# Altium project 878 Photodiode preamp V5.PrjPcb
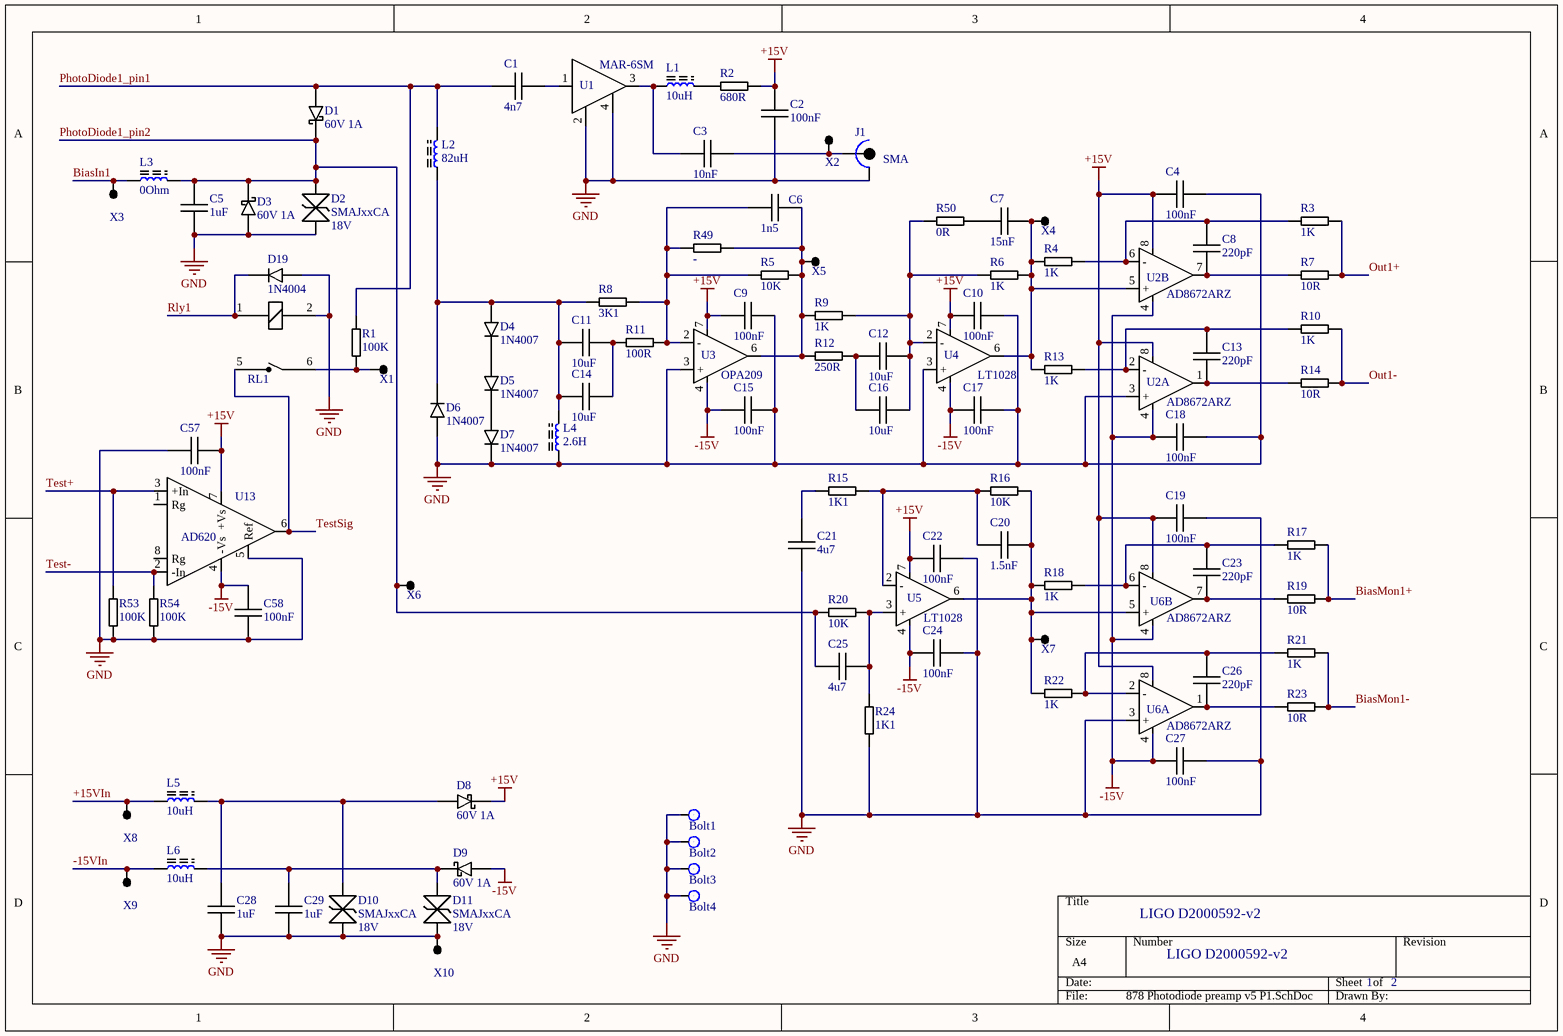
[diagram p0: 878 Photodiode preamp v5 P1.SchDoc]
2 sheets, 182 parts. Net scope: global (net labels, ports and power ports of the same name join across sheets).
Board file: 878 Photodiode preamp V5.PcbDoc
Sheets:
  878 Photodiode preamp v5 P1.SchDoc
  878 Photodiode preamp v5 P2.SchDoc

## Sheet 878 Photodiode preamp v5 P1.SchDoc
size A4

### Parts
Bolt1  Bolt M3  [BOLT]  (value not drawn)
Bolt2  Bolt M3  [BOLT]  (value not drawn)
Bolt3  Bolt M3  [BOLT]  (value not drawn)
Bolt4  Bolt M3  [BOLT]  (value not drawn)
C1  value 4n7  [HS0805Long]  (hidden comment: Cap200)
C2  value 100nF  [HS0805Long]  (hidden comment: Cap200)
C3  value 10nF  [HS0805Long]  (hidden comment: Cap200)
C4  value 100nF  [HS0805Long]  (hidden comment: Cap200)
C5  value 1uF  [HS0805Long]  (hidden comment: Cap200)
C6  value 1n5  [HS0805Long]  (hidden comment: Cap200)
C7  value 15nF  [HS0805Long]  (hidden comment: Cap200)
C8  value 220pF  [HS0805Long]  (hidden comment: Cap200)
C9  value 100nF  [HS0805Long]  (hidden comment: Cap200)
C10  value 100nF  [HS0805Long]  (hidden comment: Cap200)
C11  value 10uF  [MKS2 7.2 11]  (hidden comment: Cap200)
C12  value 10uF  [MKS2 7.2 11]  (hidden comment: Cap200)
C13  value 220pF  [HS0805Long]  (hidden comment: Cap200)
C14  value 10uF  [MKS2 7.2 11]  (hidden comment: Cap200)
C15  value 100nF  [HS0805Long]  (hidden comment: Cap200)
C16  value 10uF  [MKS2 7.2 11]  (hidden comment: Cap200)
C17  value 100nF  [HS0805Long]  (hidden comment: Cap200)
C18  value 100nF  [HS0805Long]  (hidden comment: Cap200)
C19  value 100nF  [HS0805Long]  (hidden comment: Cap200)
C20  value 1.5nF  [HS0805Long]  (hidden comment: Cap200)
C21  value 4u7  [MKS2 7.2 8.5]  (hidden comment: Cap200)
C22  value 100nF  [HS0805Long]  (hidden comment: Cap200)
C23  value 220pF  [HS0805Long]  (hidden comment: Cap200)
C24  value 100nF  [HS0805Long]  (hidden comment: Cap200)
C25  value 4u7  [MKS2 7.2 8.5]  (hidden comment: Cap200)
C26  value 220pF  [HS0805Long]  (hidden comment: Cap200)
C27  value 100nF  [HS0805Long]  (hidden comment: Cap200)
C28  value 1uF  [HS0805Long]  (hidden comment: Cap200)
C29  value 1uF  [HS0805Long]  (hidden comment: Cap200)
C57  value 100nF  [HS0805Long]  (hidden comment: Cap200)
C58  value 100nF  [HS0805Long]  (hidden comment: Cap200)
D1  60V 1A  [SOD123]
D2  SMAJxxCA  [DO214AC]
D3  60V 1A  [SOD123]
D4  1N4007  [DO214AC]
D5  1N4007  [DO214AC]
D6  1N4007  [DO214AC]
D7  1N4007  [DO214AC]
D8  60V 1A  [SOD123]
D9  60V 1A  [SOD123]
D10  SMAJxxCA  [DO214AC]
D11  SMAJxxCA  [DO214AC]
D19  1N4004  [DO214AC]
J1  SMA  [PCB SMB]
L1  value 10uH  [HS1210]  (hidden comment: Inductor)
L2  value 82uH  [HS1210]  (hidden comment: Inductor)
L3  value 0Ohm  [HS1210]  (hidden comment: Inductor)
L4  value 2.6H  [2 way 0.1"]  (hidden comment: Inductor)
L5  value 10uH  [HS1210]  (hidden comment: Inductor)
L6  value 10uH  [HS1210]  (hidden comment: Inductor)
R1  value 100K  [hs0805long]  (hidden comment: Res)
R2  value 680R  [hs0805long]  (hidden comment: Res)
R3  value 1K  [hs0805long]  (hidden comment: Res)
R4  value 1K  [hs0805long]  (hidden comment: Res)
R5  value 10K  [SpecialR]  (hidden comment: Res)
R6  value 1K  [hs0805long]  (hidden comment: Res)
R7  value 10R  [hs0805long]  (hidden comment: Res)
R8  value 3K1  [hs0805long]  (hidden comment: Res)
R9  value 1K  [hs0805long]  (hidden comment: Res)
R10  value 1K  [hs0805long]  (hidden comment: Res)
R11  value 100R  [hs0805long]  (hidden comment: Res)
R12  value 250R  [hs0805long]  (hidden comment: Res)
R13  value 1K  [hs0805long]  (hidden comment: Res)
R14  value 10R  [hs0805long]  (hidden comment: Res)
R15  value 1K1  [hs0805long]  (hidden comment: Res)
R16  value 10K  [hs0805long]  (hidden comment: Res)
R17  value 1K  [hs0805long]  (hidden comment: Res)
R18  value 1K  [hs0805long]  (hidden comment: Res)
R19  value 10R  [hs0805long]  (hidden comment: Res)
R20  value 10K  [hs0805long]  (hidden comment: Res)
R21  value 1K  [hs0805long]  (hidden comment: Res)
R22  value 1K  [hs0805long]  (hidden comment: Res)
R23  value 10R  [hs0805long]  (hidden comment: Res)
R24  value 1K1  [hs0805long]  (hidden comment: Res)
R49  Res  [hs0805long]  (value not drawn)
R50  value 0R  [hs0805long]  (hidden comment: Res)
R53  value 100K  [hs0805long]  (hidden comment: Res)
R54  value 100K  [hs0805long]  (hidden comment: Res)
RL1  9901 relay  [9901 Relay]  (value not drawn)
U1  MAR-6SM  [ww107]
U2  AD8672ARZ  [SOIC 8]  (parts A,B of 2)
U3  OPA209  [SOIC 8]
U4  LT1028  [SOIC 8]
U5  LT1028  [SOIC 8]
U6  AD8672ARZ  [SOIC 8]  (parts A,B of 2)
U13  AD620  [SOIC 8]
X1  TestPoint  [SM Test point]  (value not drawn)
X2  TestPoint  [SM Test point]  (value not drawn)
X3  TestPoint  [SM Test point]  (value not drawn)
X4  TestPoint  [SM Test point]  (value not drawn)
X5  TestPoint  [SM Test point]  (value not drawn)
X6  TestPoint  [SM Test point]  (value not drawn)
X7  TestPoint  [SM Test point]  (value not drawn)
X8  TestPoint  [SM Test point]  (value not drawn)
X9  TestPoint  [SM Test point]  (value not drawn)
X10  TestPoint  [SM Test point]  (value not drawn)

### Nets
+15V: C2.1 C4.1 C9.1 C10.1 C19.1 C22.1 C57.2 D8.K R2.2 U2.8(V+) U3.7(V+) U4.7(V+) U5.7(V+) U6.8(V+) U13.7(+Vs)
-15V: C15.1 C17.1 C18.1 C24.1 C27.1 C58.1 D9.A U2.4(V-) U3.4(V-) U4.4(V-) U5.4(V-) U6.4(V-) U13.4(-Vs)
GND: Bolt1.1 Bolt2.1 Bolt3.1 Bolt4.1 C2.2 C4.2 C5.2 C9.2 C10.2 C15.2 C17.2 C18.2 C19.2 C21.1 C22.2 C24.2 C27.2 C28.2 C29.2 C57.1 C58.2 D2.2 D3.A D6.A D7.K D10.1 D11.1 D19.A J1.2(Gnd) L4.1 R24.1 R53.1 R54.1 RL1.2(Coil-) U1.2(gnd1) U1.4(GND2) U2.3(+) U3.3(+) U4.3(+) U6.3(+) U13.5(Ref) X10.1
+15VIn: L5.1 X8.1
-15VIn: L6.1 X9.1
BiasIn1: L3.1 X3.1
BiasMon1+: R17.2 R19.2
BiasMon1-: R21.2 R23.2
Out1+: R3.2 R7.2
Out1-: R10.2 R14.2
PhotoDiode1_pin1: C1.1 D1.A L2.2 R1.2
PhotoDiode1_pin2: C5.1 C25.1 D1.K D2.1 D3.K L3.2 R20.2 X6.1
Rly1: D19.K RL1.1(Coil+)
Test+: R53.2 U13.3(+In)
Test-: R54.2 U13.2(-In)
TestSig: RL1.5(NO) U13.6(Out)
NetC1_2: C1.2 U1.1(IN)
NetC3_1: C3.1 L1.1 U1.3(OUT)
NetC3_2: C3.2 J1.1(Sig) X2.1
NetC6_1: C6.1 R5.1 R8.2 R11.2 R49.1 U3.2(-)
NetC6_2: C6.2 R5.2 R9.1 R12.1 R49.2 U3.6(OP) X5.1
NetC7_1: C7.1 R50.2
NetC7_2: C7.2 R4.1 R6.2 R13.1 U2.5(+) U4.6(OP) X4.1
NetC8_1: C8.1 R3.1 R4.2 U2.6(-)
NetC8_2: C8.2 R7.1 U2.7(OP)
NetC11_1: C11.1 C14.1 D4.A D6.K L2.1 L4.2 R8.1
NetC11_2: C11.2 C14.2 R11.1
NetC12_1: C12.1 C16.1 R12.2
NetC12_2: C12.2 C16.2 R6.1 R9.2 R50.1 U4.2(-)
NetC13_1: C13.1 R10.1 R13.2 U2.2(-)
NetC13_2: C13.2 R14.1 U2.1(OP)
NetC20_1: C20.1 R15.1 R16.1 U5.2(-)
NetC20_2: C20.2 R16.2 R18.1 R22.1 U5.6(OP) U6.5(+) X7.1
NetC21_2: C21.2 R15.2
NetC23_1: C23.1 R17.1 R18.2 U6.6(-)
NetC23_2: C23.2 R19.1 U6.7(OP)
NetC25_2: C25.2 R20.1 R24.2 U5.3(+)
NetC26_1: C26.1 R21.1 R22.2 U6.2(-)
NetC26_2: C26.2 R23.1 U6.1(OP)
NetC28_1: C28.1 D8.A D10.2 L5.2
NetC29_1: C29.1 D9.K D11.2 L6.2
NetD4_K: D4.K D5.A
NetD5_K: D5.K D7.A
NetL1_2: L1.2 R2.1
NetR1_1: R1.1 RL1.6(C) X1.1

Not connected (* = marked no-connect by the designer): U13 1(Rg) 8(Rg)

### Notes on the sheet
- LIGO D2000592-v2
- 1
- 2

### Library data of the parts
C1-C29 C57 C58 = Cap200: Cap 0.2" pitch
D1 D3 D8 D9 = Sckottky Diode: pin to pad: A>2 K>1
D2 D10 D11 = SMAJxxCA: TVS
D4-D7 D19 = 1N4004: pin to pad: A>2 K>1
J1 = PCB SMB
U2 U6 = DualOpAmp
U3-U5 = SingleOpAmp

## Sheet 878 Photodiode preamp v5 P2.SchDoc
size A4
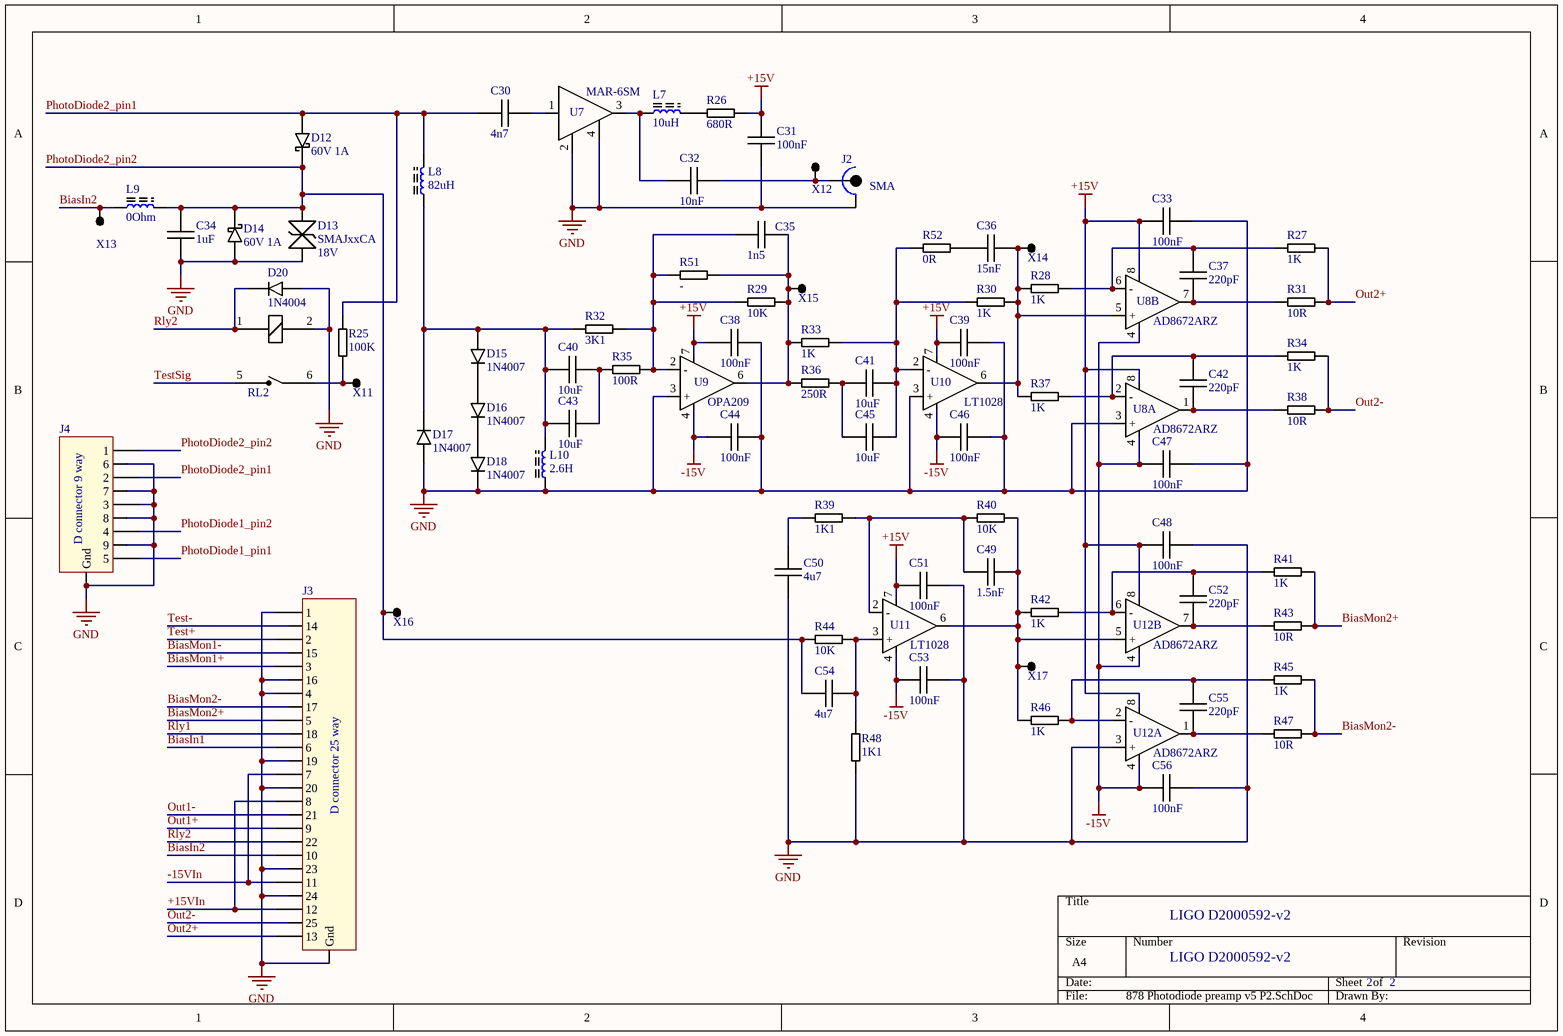
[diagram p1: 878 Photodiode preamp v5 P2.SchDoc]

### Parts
C30  value 4n7  [HS0805Long]  (hidden comment: Cap200)
C31  value 100nF  [HS0805Long]  (hidden comment: Cap200)
C32  value 10nF  [HS0805Long]  (hidden comment: Cap200)
C33  value 100nF  [HS0805Long]  (hidden comment: Cap200)
C34  value 1uF  [HS0805Long]  (hidden comment: Cap200)
C35  value 1n5  [HS0805Long]  (hidden comment: Cap200)
C36  value 15nF  [HS0805Long]  (hidden comment: Cap200)
C37  value 220pF  [HS0805Long]  (hidden comment: Cap200)
C38  value 100nF  [HS0805Long]  (hidden comment: Cap200)
C39  value 100nF  [HS0805Long]  (hidden comment: Cap200)
C40  value 10uF  [MKS2 7.2 11]  (hidden comment: Cap200)
C41  value 10uF  [MKS2 7.2 11]  (hidden comment: Cap200)
C42  value 220pF  [HS0805Long]  (hidden comment: Cap200)
C43  value 10uF  [MKS2 7.2 11]  (hidden comment: Cap200)
C44  value 100nF  [HS0805Long]  (hidden comment: Cap200)
C45  value 10uF  [MKS2 7.2 11]  (hidden comment: Cap200)
C46  value 100nF  [HS0805Long]  (hidden comment: Cap200)
C47  value 100nF  [HS0805Long]  (hidden comment: Cap200)
C48  value 100nF  [HS0805Long]  (hidden comment: Cap200)
C49  value 1.5nF  [HS0805Long]  (hidden comment: Cap200)
C50  value 4u7  [MKS2 7.2 8.5]  (hidden comment: Cap200)
C51  value 100nF  [HS0805Long]  (hidden comment: Cap200)
C52  value 220pF  [HS0805Long]  (hidden comment: Cap200)
C53  value 100nF  [HS0805Long]  (hidden comment: Cap200)
C54  value 4u7  [MKS2 7.2 8.5]  (hidden comment: Cap200)
C55  value 220pF  [HS0805Long]  (hidden comment: Cap200)
C56  value 100nF  [HS0805Long]  (hidden comment: Cap200)
D12  60V 1A  [SOD123]
D13  SMAJxxCA  [DO214AC]
D14  60V 1A  [SOD123]
D15  1N4007  [DO214AC]
D16  1N4007  [DO214AC]
D17  1N4007  [DO214AC]
D18  1N4007  [DO214AC]
D20  1N4004  [DO214AC]
J2  SMA  [PCB SMB]
J3  D connector 25 way  [D Socket Straight PCB 25 Way]
J4  D connector 9 way  [D Plug Straight PCB 9 Way]
L7  value 10uH  [HS1210]  (hidden comment: Inductor)
L8  value 82uH  [HS1210]  (hidden comment: Inductor)
L9  value 0Ohm  [HS1210]  (hidden comment: Inductor)
L10  value 2.6H  [2 way 0.1"]  (hidden comment: Inductor)
R25  value 100K  [hs0805long]  (hidden comment: Res)
R26  value 680R  [hs0805long]  (hidden comment: Res)
R27  value 1K  [hs0805long]  (hidden comment: Res)
R28  value 1K  [hs0805long]  (hidden comment: Res)
R29  value 10K  [SpecialR]  (hidden comment: Res)
R30  value 1K  [hs0805long]  (hidden comment: Res)
R31  value 10R  [hs0805long]  (hidden comment: Res)
R32  value 3K1  [hs0805long]  (hidden comment: Res)
R33  value 1K  [hs0805long]  (hidden comment: Res)
R34  value 1K  [hs0805long]  (hidden comment: Res)
R35  value 100R  [hs0805long]  (hidden comment: Res)
R36  value 250R  [hs0805long]  (hidden comment: Res)
R37  value 1K  [hs0805long]  (hidden comment: Res)
R38  value 10R  [hs0805long]  (hidden comment: Res)
R39  value 1K1  [hs0805long]  (hidden comment: Res)
R40  value 10K  [hs0805long]  (hidden comment: Res)
R41  value 1K  [hs0805long]  (hidden comment: Res)
R42  value 1K  [hs0805long]  (hidden comment: Res)
R43  value 10R  [hs0805long]  (hidden comment: Res)
R44  value 10K  [hs0805long]  (hidden comment: Res)
R45  value 1K  [hs0805long]  (hidden comment: Res)
R46  value 1K  [hs0805long]  (hidden comment: Res)
R47  value 10R  [hs0805long]  (hidden comment: Res)
R48  value 1K1  [hs0805long]  (hidden comment: Res)
R51  Res  [hs0805long]  (value not drawn)
R52  value 0R  [hs0805long]  (hidden comment: Res)
RL2  9901 relay  [9901 Relay]  (value not drawn)
U7  MAR-6SM  [ww107]
U8  AD8672ARZ  [SOIC 8]  (parts A,B of 2)
U9  OPA209  [SOIC 8]
U10  LT1028  [SOIC 8]
U11  LT1028  [SOIC 8]
U12  AD8672ARZ  [SOIC 8]  (parts A,B of 2)
X11  TestPoint  [SM Test point]  (value not drawn)
X12  TestPoint  [SM Test point]  (value not drawn)
X13  TestPoint  [SM Test point]  (value not drawn)
X14  TestPoint  [SM Test point]  (value not drawn)
X15  TestPoint  [SM Test point]  (value not drawn)
X16  TestPoint  [SM Test point]  (value not drawn)
X17  TestPoint  [SM Test point]  (value not drawn)

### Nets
+15V: C31.1 C33.1 C38.1 C39.1 C48.1 C51.1 R26.2 U8.8(V+) U9.7(V+) U10.7(V+) U11.7(V+) U12.8(V+)
-15V: C44.1 C46.1 C47.1 C53.1 C56.1 U8.4(V-) U9.4(V-) U10.4(V-) U11.4(V-) U12.4(V-)
GND: C31.2 C33.2 C34.2 C38.2 C39.2 C44.2 C46.2 C47.2 C48.2 C50.1 C51.2 C53.2 C56.2 D13.2 D14.A D17.A D18.K D20.A J2.2(Gnd) J3.1 J3.4 J3.16 J3.19 J3.20 J3.23 J3.24 J3.26(Gnd) J4.3 J4.6 J4.7 J4.8 J4.9 J4.10(Gnd) L10.1 R48.1 RL2.2(Coil-) U7.2(gnd1) U7.4(GND2) U8.3(+) U9.3(+) U10.3(+) U12.3(+)
+15VIn: J3.8 J3.12
-15VIn: J3.7 J3.11
BiasIn1: J3.6
BiasIn2: J3.10 L9.1 X13.1
BiasMon1+: J3.3
BiasMon1-: J3.15
BiasMon2+: J3.5 R41.2 R43.2
BiasMon2-: J3.17 R45.2 R47.2
Out1+: J3.9
Out1-: J3.21
Out2+: J3.13 R27.2 R31.2
Out2-: J3.25 R34.2 R38.2
PhotoDiode1_pin1: J4.5
PhotoDiode1_pin2: J4.4
PhotoDiode2_pin1: C30.1 D12.A J4.2 L8.2 R25.2
PhotoDiode2_pin2: C34.1 C54.1 D12.K D13.1 D14.K J4.1 L9.2 R44.2 X16.1
Rly1: J3.18
Rly2: D20.K J3.22 RL2.1(Coil+)
Test+: J3.2
Test-: J3.14
TestSig: RL2.5(NO)
NetC30_2: C30.2 U7.1(IN)
NetC32_1: C32.1 L7.1 U7.3(OUT)
NetC32_2: C32.2 J2.1(Sig) X12.1
NetC35_1: C35.1 R29.1 R32.2 R35.2 R51.1 U9.2(-)
NetC35_2: C35.2 R29.2 R33.1 R36.1 R51.2 U9.6(OP) X15.1
NetC36_1: C36.1 R52.2
NetC36_2: C36.2 R28.1 R30.2 R37.1 U8.5(+) U10.6(OP) X14.1
NetC37_1: C37.1 R27.1 R28.2 U8.6(-)
NetC37_2: C37.2 R31.1 U8.7(OP)
NetC40_1: C40.1 C43.1 D15.A D17.K L8.1 L10.2 R32.1
NetC40_2: C40.2 C43.2 R35.1
NetC41_1: C41.1 C45.1 R36.2
NetC41_2: C41.2 C45.2 R30.1 R33.2 R52.1 U10.2(-)
NetC42_1: C42.1 R34.1 R37.2 U8.2(-)
NetC42_2: C42.2 R38.1 U8.1(OP)
NetC49_1: C49.1 R39.1 R40.1 U11.2(-)
NetC49_2: C49.2 R40.2 R42.1 R46.1 U11.6(OP) U12.5(+) X17.1
NetC50_2: C50.2 R39.2
NetC52_1: C52.1 R41.1 R42.2 U12.6(-)
NetC52_2: C52.2 R43.1 U12.7(OP)
NetC54_2: C54.2 R44.1 R48.2 U11.3(+)
NetC55_1: C55.1 R45.1 R46.2 U12.2(-)
NetC55_2: C55.2 R47.1 U12.1(OP)
NetD15_K: D15.K D16.A
NetD16_K: D16.K D18.A
NetL7_2: L7.2 R26.1
NetR25_1: R25.1 RL2.6(C) X11.1

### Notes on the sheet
- LIGO D2000592-v2
- 2

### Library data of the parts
C30-C56 = Cap200: Cap 0.2" pitch
D12 D14 = Sckottky Diode: pin to pad: A>2 K>1
D13 = SMAJxxCA: TVS
D15-D18 D20 = 1N4004: pin to pad: A>2 K>1
J2 = PCB SMB
U8 U12 = DualOpAmp
U9-U11 = SingleOpAmp

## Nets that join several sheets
+15V: 878 Photodiode preamp v5 P1 (15 pins), 878 Photodiode preamp v5 P2 (12 pins)
-15V: 878 Photodiode preamp v5 P1 (13 pins), 878 Photodiode preamp v5 P2 (10 pins)
GND: 878 Photodiode preamp v5 P1 (42 pins), 878 Photodiode preamp v5 P2 (42 pins)
+15VIn: 878 Photodiode preamp v5 P1 (L5.1 X8.1), 878 Photodiode preamp v5 P2 (J3.8 J3.12)
-15VIn: 878 Photodiode preamp v5 P1 (L6.1 X9.1), 878 Photodiode preamp v5 P2 (J3.7 J3.11)
BiasIn1: 878 Photodiode preamp v5 P1 (L3.1 X3.1), 878 Photodiode preamp v5 P2 (J3.6)
BiasMon1+: 878 Photodiode preamp v5 P1 (R17.2 R19.2), 878 Photodiode preamp v5 P2 (J3.3)
BiasMon1-: 878 Photodiode preamp v5 P1 (R21.2 R23.2), 878 Photodiode preamp v5 P2 (J3.15)
Out1+: 878 Photodiode preamp v5 P1 (R3.2 R7.2), 878 Photodiode preamp v5 P2 (J3.9)
Out1-: 878 Photodiode preamp v5 P1 (R10.2 R14.2), 878 Photodiode preamp v5 P2 (J3.21)
PhotoDiode1_pin1: 878 Photodiode preamp v5 P1 (C1.1 D1.A L2.2 R1.2), 878 Photodiode preamp v5 P2 (J4.5)
PhotoDiode1_pin2: 878 Photodiode preamp v5 P1 (8 pins), 878 Photodiode preamp v5 P2 (J4.4)
Rly1: 878 Photodiode preamp v5 P1 (D19.K RL1.1), 878 Photodiode preamp v5 P2 (J3.18)
Test+: 878 Photodiode preamp v5 P1 (R53.2 U13.3), 878 Photodiode preamp v5 P2 (J3.2)
Test-: 878 Photodiode preamp v5 P1 (R54.2 U13.2), 878 Photodiode preamp v5 P2 (J3.14)
TestSig: 878 Photodiode preamp v5 P1 (RL1.5 U13.6), 878 Photodiode preamp v5 P2 (RL2.5)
